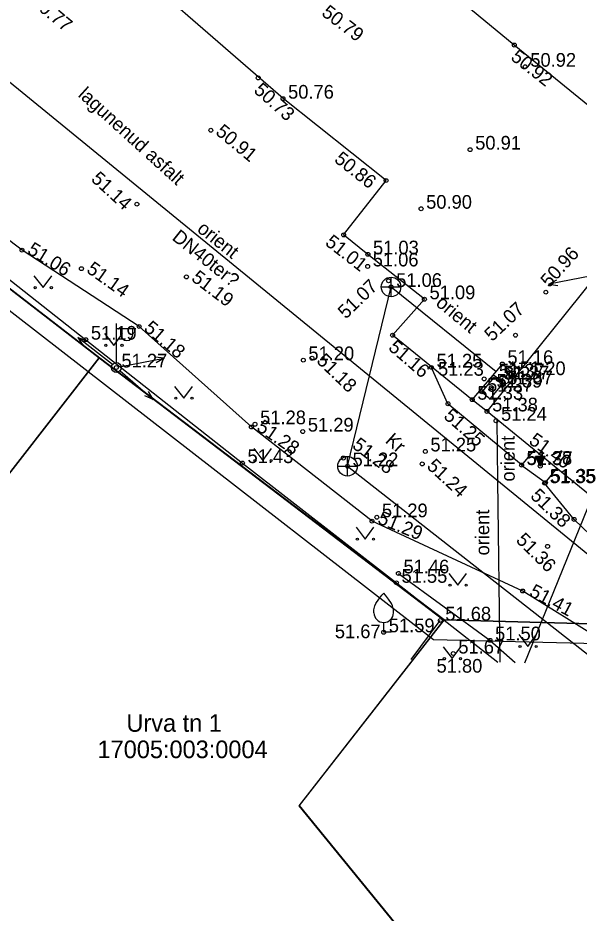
# Model space of a CAD drawing. Extents: x 640876 to 641418, y 6455595 to 6456085.
# Drawn here: x 641115.1 to 641143.81, y 6455774.33 to 6455820.12 of the extents above; entities that cross this region are included whole.
import ezdxf

# ---------------------------------------------------------------- set-up
doc = ezdxf.new("R2010")
doc.units = 0
for name, color, linetype in [('AED', 7, 'Continuous'), ('HALJASTUS', 7, 'Continuous'), ('HOONE', 7, 'Continuous'), ('HOONEDET', 7, 'Continuous'), ('KKAEV', 7, 'Continuous'), ('KORGUS', 7, 'Continuous'), ('KTRASS', 7, 'Continuous'), ('MOOTKORG', 7, 'Continuous'), ('MOOTMPUNKT', 7, 'Continuous'), ('MOOTPIIR', 7, 'Continuous'), ('MPOHULIIN', 7, 'Continuous'), ('PIIR', 7, 'Continuous'), ('POST', 7, 'Continuous'), ('PUU', 7, 'Continuous'), ('RAJATIS', 7, 'Continuous'), ('SITRASS', 7, 'Continuous'), ('TEE', 7, 'Continuous'), ('VTRASS', 7, 'Continuous')]:
    doc.layers.add(name, color=color, linetype=linetype)

msp = doc.modelspace()

# ---------------------------------------------------------------- linework, layer by layer
at = {"layer": 'AED'}
msp.add_line((641135.211, 6455787.301), (641136.702, 6455789.299), dxfattribs=at)
msp.add_lwpolyline([(641099.859, 6455819.896), (641099.12, 6455818.953), (641105.695, 6455813.799), (641118.57, 6455803.662), (641126.581, 6455797.35), (641134.461, 6455791.227), (641139.651, 6455787.174)], dxfattribs=at)
at = {"layer": 'HALJASTUS'}
for p, q in [((641115.918, 6455806.931), (641116.381, 6455806.324)), ((641116.381, 6455806.324), (641116.827, 6455806.931)), ((641119.532, 6455803.978), (641119.996, 6455803.371)), ((641119.996, 6455803.371), (641120.441, 6455803.978)), ((641123.114, 6455801.274), (641123.577, 6455800.667)), ((641123.577, 6455800.667), (641124.023, 6455801.274)), ((641127.159, 6455798.089), (641127.623, 6455797.482)), ((641127.623, 6455797.482), (641128.068, 6455798.089)), ((641132.399, 6455794.066), (641132.862, 6455793.459)), ((641132.862, 6455793.459), (641133.308, 6455794.066)), ((641137.141, 6455791.71), (641137.604, 6455791.103)), ((641137.604, 6455791.103), (641138.05, 6455791.71)), ((641140.722, 6455788.579), (641141.185, 6455787.972)), ((641141.185, 6455787.972), (641141.631, 6455788.579)), ((641136.85, 6455787.958), (641137.314, 6455787.351)), ((641137.314, 6455787.351), (641137.759, 6455787.958))]:
    msp.add_line(p, q, dxfattribs=at)
msp.add_lwpolyline([(641134.561, 6455791.709), (641139.247, 6455788.285), (641140.527, 6455787.149)], dxfattribs=at)
for centre in [(641115.98, 6455806.324), (641116.809, 6455806.324), (641119.595, 6455803.371), (641120.423, 6455803.371), (641123.176, 6455800.667), (641124.005, 6455800.667), (641127.222, 6455797.482), (641128.05, 6455797.482), (641132.461, 6455793.459), (641133.29, 6455793.459), (641137.203, 6455791.103), (641138.032, 6455791.103), (641140.784, 6455787.972), (641141.613, 6455787.972), (641136.913, 6455787.351), (641137.742, 6455787.351)]:
    msp.add_circle(centre, 0.055, dxfattribs=at)
at = {"layer": 'HOONE'}
for points in [[(641139.149, 6455869.673), (641123.276, 6455850.742), (641124.076, 6455850.041), (641120.776, 6455845.978), (641123.157, 6455844.065), (641125.741, 6455841.899), (641129.074, 6455839.178), (641138.729, 6455831.239), (641154.511, 6455818.271), (641155.863, 6455817.162), (641166.356, 6455808.477), (641157.088, 6455797.138), (641158.337, 6455796.148), (641152.522, 6455789.036), (641139.095, 6455799.993), (641148.747, 6455811.989), (641140.492, 6455818.73), (641127.295, 6455829.597), (641115.375, 6455839.33), (641112.285, 6455835.53)], [(641141.501, 6455798.03), (641140.862, 6455797.247), (641142.084, 6455796.351), (641142.673, 6455797.073)]]:
    msp.add_lwpolyline(points, dxfattribs=at)
at = {"layer": 'HOONEDET'}
for p, q in [((641141.818, 6455797.197), (641141.572, 6455797.684)), ((641142.064, 6455797.684), (641141.572, 6455797.684)), ((641141.58, 6455797.667), (641141.924, 6455797.406)), ((641141.599, 6455797.684), (641141.935, 6455797.428)), ((641141.606, 6455797.616), (641141.912, 6455797.383)), ((641141.632, 6455797.565), (641141.901, 6455797.36)), ((641141.641, 6455797.684), (641141.947, 6455797.451)), ((641141.658, 6455797.514), (641141.889, 6455797.338)), ((641141.682, 6455797.684), (641141.958, 6455797.474)), ((641141.683, 6455797.463), (641141.878, 6455797.315)), ((641141.709, 6455797.412), (641141.866, 6455797.292)), ((641141.723, 6455797.684), (641141.97, 6455797.496)), ((641141.735, 6455797.36), (641141.855, 6455797.27)), ((641141.764, 6455797.684), (641141.981, 6455797.519)), ((641141.806, 6455797.684), (641141.992, 6455797.542)), ((641141.818, 6455797.197), (641142.064, 6455797.684)), ((641141.847, 6455797.684), (641142.004, 6455797.564)), ((641141.888, 6455797.684), (641142.015, 6455797.587)), ((641141.929, 6455797.684), (641142.027, 6455797.61)), ((641141.971, 6455797.684), (641142.038, 6455797.632)), ((641142.012, 6455797.684), (641142.05, 6455797.655)), ((641142.053, 6455797.684), (641142.061, 6455797.678)), ((641141.761, 6455797.309), (641141.843, 6455797.247)), ((641141.787, 6455797.258), (641141.832, 6455797.224)), ((641141.813, 6455797.207), (641141.82, 6455797.201))]:
    msp.add_line(p, q, dxfattribs=at)
at = {"layer": 'KKAEV'}
for p, q in [((641134.186, 6455805.86), (641134.186, 6455806.86)), ((641133.686, 6455806.36), (641134.686, 6455806.36)), ((641131.956, 6455796.689), (641131.956, 6455797.689)), ((641131.456, 6455797.189), (641132.456, 6455797.189))]:
    msp.add_line(p, q, dxfattribs=at)
for centre in [(641134.186, 6455806.36), (641131.956, 6455797.189)]:
    msp.add_circle(centre, 0.5, dxfattribs=at)
at = {"layer": 'KORGUS'}
for centre in [(641140.492, 6455818.73), (641127.392, 6455817.049), (641124.965, 6455814.372), (641138.23, 6455813.382), (641133.931, 6455811.803), (641121.182, 6455810.593), (641135.721, 6455810.359), (641131.761, 6455809.021), (641115.306, 6455808.241), (641118.345, 6455807.292), (641123.717, 6455806.872), (641134.061, 6455806.676), (641142.105, 6455806.092), (641121.299, 6455804.336), (641134.265, 6455803.889), (641140.553, 6455803.889), (641130.143, 6455802.713), (641138.949, 6455801.655), (641137.098, 6455800.384), (641139.095, 6455799.993), (641127.043, 6455799.198), (641131.745, 6455797.608), (641135.781, 6455797.306), (641133.213, 6455794.381), (641143.551, 6455794.471), (641142.192, 6455793.09), (641140.92, 6455790.807)]:
    msp.add_circle(centre, 0.1, dxfattribs=at)
at = {"layer": 'KTRASS'}
for p, q in [((641131.956, 6455797.189), (641134.186, 6455806.36)), ((641134.186, 6455806.36), (641139.559, 6455802.037)), ((641131.956, 6455797.189), (641144.933, 6455787.023))]:
    msp.add_line(p, q, dxfattribs=at)
at = {"layer": 'MOOTMPUNKT'}
for centre in [(641141.048, 6455817.622), (641128.658, 6455815.989), (641133.001, 6455808.025), (641132.987, 6455807.409), (641134.186, 6455806.36), (641135.895, 6455805.73), (641118.57, 6455803.662), (641129.697, 6455802.613), (641139.879, 6455802.417), (641120.132, 6455802.239), (641136.252, 6455802.238), (641140.513, 6455801.848), (641139.445, 6455801.73), (641139.672, 6455801.627), (641139.869, 6455801.376), (641138.836, 6455800.998), (641139.321, 6455801.213), (641138.34, 6455800.592), (641127.227, 6455799.336), (641139.553, 6455799.514), (641129.668, 6455798.963), (641135.938, 6455797.946), (641126.581, 6455797.35), (641140.862, 6455797.247), (641131.956, 6455797.189), (641141.818, 6455797.197), (641142.04, 6455796.323), (641142.084, 6455796.351), (641133.458, 6455794.58), (641134.561, 6455791.709), (641134.461, 6455791.227), (641136.702, 6455789.299), (641133.81, 6455788.697), (641139.247, 6455788.285), (641137.369, 6455787.611)]:
    msp.add_circle(centre, 0.1, dxfattribs=at)
at = {"layer": 'MOOTPIIR'}
msp.add_lwpolyline([(641060.916, 6455895.936), (641100.061, 6455950.482), (641099.586, 6455952.159), (641069.132, 6455984.035), (641066.132, 6455988.623), (641076.463, 6456005.049), (641230.642, 6456010.048), (641237.36, 6455995.24), (641237.24, 6455992.81), (641236.258, 6455990.888), (641229.041, 6455971.315), (641203.026, 6455909.57), (641225.257, 6455906.847), (641239.512, 6455898.491), (641200.195, 6455851.697), (641192.016, 6455859.099), (641169.785, 6455829.138), (641192.025, 6455807.568), (641252.96, 6455758.075), (641231.388, 6455736.74), (641191.474, 6455775.975), (641152.419, 6455787.914), (641136.351, 6455788.307), (641049.066, 6455856.043)], dxfattribs=at)
at = {"layer": 'MPOHULIIN'}
for p, q in [((641144.46, 6455806.919), (641142.251, 6455806.494)), ((641142.251, 6455806.494), (641142.666, 6455806.725)), ((641142.251, 6455806.494), (641142.722, 6455806.431)), ((641118.161, 6455803.777), (641118.424, 6455803.381)), ((641118.161, 6455803.777), (641118.609, 6455803.616)), ((641119.935, 6455802.393), (641118.161, 6455803.777)), ((641120.377, 6455802.286), (641122.587, 6455802.711)), ((641122.587, 6455802.711), (641122.116, 6455802.774)), ((641122.587, 6455802.711), (641122.171, 6455802.48)), ((641120.132, 6455802.239), (641120.132, 6455802.239)), ((641120.132, 6455802.239), (641120.132, 6455802.239)), ((641120.132, 6455802.239), (641120.132, 6455802.239)), ((641120.321, 6455802.075), (641122.02, 6455800.6)), ((641122.02, 6455800.6), (641121.778, 6455801.009)), ((641122.02, 6455800.6), (641121.581, 6455800.784))]:
    msp.add_line(p, q, dxfattribs=at)
at = {"layer": 'PIIR'}
for points in [[(641216.67, 6455752.61), (641192, 6455776.86), (641152.58, 6455788.91), (641136.9, 6455789.33), (641119.28, 6455802.72), (641101.72, 6455816.27), (641098.61, 6455818.83), (641124.03, 6455849.78), (641139.51, 6455868.99), (641157, 6455885.69), (641191.84, 6455860.59), (641168.46, 6455829.03), (641191.37, 6455806.79), (641234.69, 6455771.62)], [(641099.43, 6455777.27), (641081.98, 6455790.7), (641101.69, 6455816.28), (641119.25, 6455802.74)], [(641129.48, 6455779.84), (641138.9, 6455768.3), (641127.85, 6455755.11), (641099.43, 6455777.27), (641119.25, 6455802.74), (641136.89, 6455789.31)], [(641216.67, 6455752.61), (641182.28, 6455716.38), (641177.47, 6455716.39), (641127.83, 6455755.09), (641138.89, 6455768.28), (641129.48, 6455779.82), (641136.9, 6455789.33), (641152.58, 6455788.91), (641192, 6455776.86)]]:
    msp.add_lwpolyline(points, close=True, dxfattribs=at)
at = {"layer": 'POST'}
for p, q in [((641120.132, 6455802.489), (641120.132, 6455804.489)), ((641120.132, 6455804.239), (641121.132, 6455804.239)), ((641120.359, 6455803.918), (641120.359, 6455804.239)), ((641120.971, 6455803.918), (641120.971, 6455804.239)), ((641120.132, 6455802.239), (641120.132, 6455802.239))]:
    msp.add_line(p, q, dxfattribs=at)
msp.add_circle((641120.132, 6455802.239), 0.25, dxfattribs=at)
msp.add_arc((641120.665, 6455803.918), 0.306, 180, 0, dxfattribs=at)
at = {"layer": 'PUU'}
for p, q in [((641133.81, 6455788.697), (641133.81, 6455789.197)), ((641134.21, 6455788.697), (641133.81, 6455788.697))]:
    msp.add_line(p, q, dxfattribs=at)
for points in [[(641133.31, 6455789.697), (641133.31, 6455789.847), (641133.32, 6455789.912), (641133.355, 6455790.042), (641133.415, 6455790.162), (641133.56, 6455790.397), (641133.72, 6455790.602), (641133.81, 6455790.697)], [(641134.31, 6455789.697), (641134.31, 6455789.847), (641134.3, 6455789.912), (641134.265, 6455790.042), (641134.205, 6455790.162), (641134.06, 6455790.397), (641133.9, 6455790.602), (641133.81, 6455790.697)]]:
    msp.add_lwpolyline(points, dxfattribs=at)
msp.add_arc((641133.81, 6455789.697), 0.5, 180, 0, dxfattribs=at)
at = {"layer": 'RAJATIS'}
for points in [[(641139.095, 6455799.993), (641138.34, 6455800.592), (641139.879, 6455802.417), (641140.556, 6455801.809)], [(641139.869, 6455801.376), (641139.445, 6455801.73), (641138.836, 6455800.998), (641139.26, 6455800.644), (641139.869, 6455801.376)]]:
    msp.add_lwpolyline(points, dxfattribs=at)
at = {"layer": 'SITRASS'}
msp.add_lwpolyline([(641141.028, 6455787.135), (641144.48, 6455795.599)], dxfattribs=at)
at = {"layer": 'TEE'}
for points in [[(641138.34, 6455800.592), (641134.265, 6455803.889), (641135.895, 6455805.73), (641133.001, 6455808.025), (641131.761, 6455809.021), (641133.931, 6455811.803), (641128.658, 6455815.989), (641118.513, 6455824.816), (641109.861, 6455831.873)], [(641146.099, 6455786.99), (641144.934, 6455788.318), (641140.92, 6455790.807), (641133.213, 6455794.381), (641127.043, 6455799.198), (641121.299, 6455804.336), (641115.306, 6455808.241), (641107.025, 6455814.477), (641099.665, 6455819.667)], [(641140.851, 6455797.265), (641137.098, 6455800.384), (641136.221, 6455802.307)], [(641152.522, 6455789.036), (641150.717, 6455788.551), (641147.201, 6455790.973), (641143.551, 6455794.471), (641142.04, 6455796.323)]]:
    msp.add_lwpolyline(points, dxfattribs=at)
at = {"layer": 'VTRASS'}
for p, q in [((641139.598, 6455799.583), (641139.637, 6455796.45)), ((641139.637, 6455796.45), (641139.753, 6455787.171))]:
    msp.add_line(p, q, dxfattribs=at)
msp.add_lwpolyline([(641123.713, 6455832.522), (641112.411, 6455818.681), (641151.409, 6455786.838)], dxfattribs=at)

# ---------------------------------------------------------------- texts
at = {"layer": 'HOONEDET'}
msp.add_text(' 51.40', height=0.7, rotation=324.0921, dxfattribs=at).set_placement((641140.976, 6455798.541))
at = {"layer": 'KORGUS'}
for s, rotation, p in [(' 50.77', 320.1888, (641115.514, 6455821.03)), (' 50.79', 322.5843, (641130.379, 6455820.442)), (' 50.92', 321.8059, (641140.059, 6455818.18)), (' 50.73', 318.156, (641126.925, 6455816.528)), (' 50.91', 320.3465, (641124.965, 6455814.372)), (' 50.86', 321.5873, (641131.032, 6455812.96)), (' 51.14', 317.4539, (641118.605, 6455811.996)), (' 51.01', 322.1789, (641130.563, 6455808.7)), (' 51.06', 328.2436, (641115.306, 6455808.241)), (' 50.96', 47.9129, (641142.105, 6455806.092)), (' 51.14', 324.5759, (641118.345, 6455807.292)), (' 51.19', 322.852, (641123.717, 6455806.872)), (' 51.07', 43.924, (641131.683, 6455804.508)), (' 51.07', 43.2751, (641139.17, 6455803.358)), (' 51.18', 319.522, (641121.299, 6455804.336)), (' 51.16', 319.0947, (641133.807, 6455803.36)), (' 51.18', 316.018, (641130.143, 6455802.713)), (' 51.25', 318.7792, (641136.637, 6455799.857)), (' 51.28', 325.6338, (641127.043, 6455799.198)), (' 51.28', 322.7543, (641131.944, 6455798.32)), (' 51.24', 317.2786, (641135.781, 6455797.306)), (' 51.38', 316.1201, (641141.084, 6455795.797)), (' 51.29', 337.645, (641133.213, 6455794.381)), (' 51.36', 315.2752, (641140.351, 6455793.545)), (' 51.41', 331.9259, (641140.98, 6455790.708))]:
    msp.add_text(s, height=0.7, rotation=rotation, dxfattribs=at).set_placement(p)
for s, p in [(' 50.91', (641138.23, 6455813.382)), (' 50.90', (641135.721, 6455810.359)), (' 51.23', (641136.329, 6455801.818)), (' 51.38', (641139.095, 6455799.993)), (' 51.67', (641131.049, 6455788.394))]:
    msp.add_text(s, height=0.7, dxfattribs=at).set_placement(p)
at = {"layer": 'KTRASS'}
msp.add_text('orient', height=0.7, rotation=320.3084, dxfattribs=at).set_placement((641136.426, 6455805.451))
at = {"layer": 'MOOTKORG'}
for s, p in [(' 50.92', (641141.048, 6455817.622)), (' 50.76', (641128.658, 6455815.989)), (' 51.03', (641133.001, 6455808.025)), (' 51.06', (641132.987, 6455807.409)), (' 51.06', (641134.186, 6455806.36)), (' 51.09', (641135.895, 6455805.73)), (' 51.19', (641118.57, 6455803.662)), (' 51.20', (641129.697, 6455802.613)), (' 51.27', (641120.132, 6455802.239)), (' 51.25', (641136.252, 6455802.238)), (' 51.16', (641139.879, 6455802.417)), (' 51.37', (641139.445, 6455801.73)), (' 51.20', (641140.513, 6455801.848)), (' 51.39', (641139.321, 6455801.213)), (' 51.37', (641139.672, 6455801.627)), (' 51.37', (641139.869, 6455801.376)), (' 51.37', (641138.836, 6455800.998)), (' 51.33', (641138.34, 6455800.592)), (' 51.24', (641139.553, 6455799.514)), (' 51.28', (641127.227, 6455799.336)), (' 51.29', (641129.668, 6455798.963)), (' 51.25', (641135.938, 6455797.946)), (' 51.43', (641126.581, 6455797.35)), (' 51.22', (641131.956, 6455797.189)), (' 51.38', (641140.851, 6455797.265)), (' 51.37', (641140.862, 6455797.247)), (' 51.35', (641142.04, 6455796.323)), (' 51.35', (641142.084, 6455796.351)), (' 51.29', (641133.458, 6455794.58)), (' 51.46', (641134.561, 6455791.709)), (' 51.55', (641134.461, 6455791.227)), (' 51.68', (641136.702, 6455789.299)), (' 51.59', (641133.81, 6455788.697)), (' 51.50', (641139.247, 6455788.285)), (' 51.67', (641137.369, 6455787.611)), (' 51.80', (641136.252, 6455786.631))]:
    msp.add_text(s, height=0.7, dxfattribs=at).set_placement(p)
at = {"layer": 'PIIR'}
for s, p in [('Urva tn 1', (641120.649, 6455783.608)), ('17005:003:0004', (641119.17, 6455782.26))]:
    msp.add_text(s, height=0.9, dxfattribs=at).set_placement(p)
at = {"layer": 'RAJATIS'}
msp.add_text('bet', height=0.7, rotation=50.144, dxfattribs=at).set_placement((641140.005, 6455801.239))
at = {"layer": 'TEE'}
for s, p in [('lagunenud asfalt', (641118.134, 6455816.133)), ('Kr', (641133.849, 6455798.442))]:
    msp.add_text(s, height=0.7, rotation=317.8346, dxfattribs=at).set_placement(p)
at = {"layer": 'VTRASS'}
for s, rotation, p in [('DN40ter?', 321.3812, (641122.937, 6455808.807)), ('orient', 321.3812, (641124.216, 6455809.232)), ('orient', 90, (641140.51, 6455796.405)), ('orient', 90, (641139.208, 6455792.627))]:
    msp.add_text(s, height=0.7, rotation=rotation, dxfattribs=at).set_placement(p)

doc.saveas('drawing.dxf')
